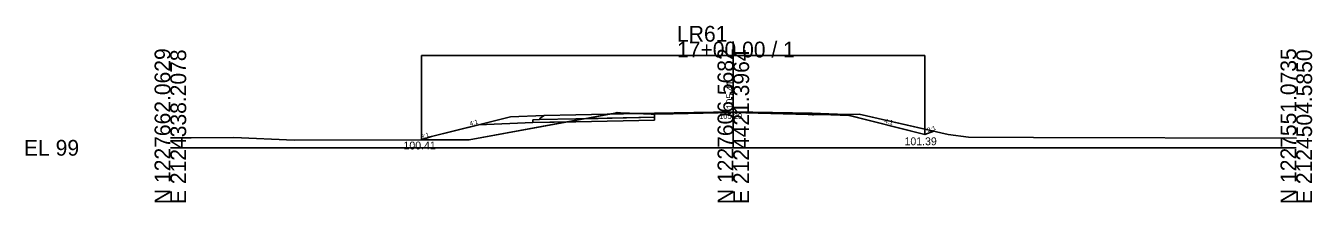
# Model space of a CAD drawing. Extents: x 2121193 to 2127979, y 1225108 to 1234639.
# Drawn here: x 2127750.9 to 2127979.4, y 1232107.5 to 1232138.9 of the extents above; entities that cross this region are included whole.
import ezdxf

# ---------------------------------------------------------------- set-up
doc = ezdxf.new("R2010")
doc.units = 0
for name, color, linetype in [('XS_CELL', 7, 'Continuous'), ('XS_M_DITCH', 7, 'Continuous'), ('XS_M_SHAPES_EARTHWORK', 7, 'Continuous'), ('XS_P_FINISHED_GRADE', 7, 'Continuous'), ('XS_P_FINISHED_GRADE_ELEV_TX', 7, 'Continuous'), ('XS_P_SUBGRADE_GRANULAR', 7, 'Continuous'), ('XS_P_SUBGRADE_LEVELING', 7, 'Continuous'), ('XS_P_SUBGRADE_PAVEMENT', 7, 'Continuous'), ('XS_P_TX_DCH', 7, 'Continuous'), ('XS_P_TX_FS_BS', 7, 'Continuous'), ('XS_X_GROUND', 7, 'Continuous'), ('XS_X_GROUND_TX', 7, 'Continuous')]:
    doc.layers.add(name, color=color, linetype=linetype)

msp = doc.modelspace()

# ---------------------------------------------------------------- linework, layer by layer
at = {"layer": 'XS_CELL'}
for p, q in [((2127876.61, 1232117.21), (2127876.61, 1232136.08)), ((2127776.61, 1232117.21), (2127876.61, 1232117.21)), ((2127876.61, 1232117.21), (2127976.61, 1232117.21))]:
    msp.add_line(p, q, dxfattribs=at)
at = {"layer": 'XS_M_DITCH'}
for p, q in [((2127821.24, 1232118.62), (2127821.24, 1232133.62)), ((2127821.24, 1232133.62), (2127910.61, 1232133.62)), ((2127910.61, 1232133.62), (2127910.61, 1232119.6))]:
    msp.add_line(p, q, dxfattribs=at)
at = {"layer": 'XS_M_SHAPES_EARTHWORK'}
for p, q in [((2127850.14, 1232122.38), (2127847.06, 1232121.82)), ((2127850.14, 1232122.38), (2127847.06, 1232121.82)), ((2127848.61, 1232121.85), (2127862.61, 1232122.13)), ((2127848.61, 1232121.85), (2127862.61, 1232122.13)), ((2127854.51, 1232123.18), (2127850.14, 1232122.38)), ((2127850.14, 1232122.38), (2127862.61, 1232122.63)), ((2127862.61, 1232122.63), (2127850.14, 1232122.38)), ((2127862.61, 1232122.63), (2127850.14, 1232122.38)), ((2127855.6, 1232123.38), (2127854.51, 1232123.18)), ((2127854.51, 1232123.18), (2127859.76, 1232123.28)), ((2127859.76, 1232123.28), (2127854.51, 1232123.18)), ((2127855.97, 1232123.47), (2127855.6, 1232123.38)), ((2127856.59, 1232123.44), (2127855.97, 1232123.47)), ((2127859.76, 1232123.28), (2127856.59, 1232123.44)), ((2127861.99, 1232123.17), (2127859.76, 1232123.28)), ((2127862.61, 1232123.18), (2127861.99, 1232123.17)), ((2127862.61, 1232122.63), (2127862.61, 1232123.18)), ((2127862.61, 1232122.13), (2127862.61, 1232122.63)), ((2127862.61, 1232122.13), (2127862.61, 1232122.63)), ((2127890.68, 1232123.21), (2127890.68, 1232123.08)), ((2127893.31, 1232123.11), (2127890.68, 1232123.21)), ((2127890.68, 1232123.08), (2127890.86, 1232123.07)), ((2127890.86, 1232123.07), (2127893.31, 1232123.11)), ((2127894.04, 1232123.12), (2127893.31, 1232123.11)), ((2127893.31, 1232123.11), (2127897.2, 1232122.95)), ((2127895.61, 1232123.14), (2127894.04, 1232123.12)), ((2127898.99, 1232123.19), (2127895.61, 1232123.14)), ((2127896.61, 1232123.1), (2127895.61, 1232123.14)), ((2127895.61, 1232123.14), (2127896.61, 1232123.1)), ((2127897.2, 1232122.95), (2127896.61, 1232123.1)), ((2127912.22, 1232120.14), (2127898.99, 1232123.19)), ((2127831.43, 1232121.32), (2127823, 1232119.21)), ((2127829.69, 1232118.65), (2127847.06, 1232121.82)), ((2127841, 1232121.7), (2127831.43, 1232121.32)), ((2127847.06, 1232121.82), (2127841, 1232121.7)), ((2127847.06, 1232121.82), (2127848.61, 1232121.85)), ((2127847.06, 1232121.82), (2127848.61, 1232121.85)), ((2127910.61, 1232119.6), (2127912.22, 1232120.14)), ((2127823, 1232119.21), (2127821.24, 1232118.62)), ((2127821.24, 1232118.62), (2127829.69, 1232118.65))]:
    msp.add_line(p, q, dxfattribs=at)
msp.add_lwpolyline([(2127896.61, 1232123.1), (2127897.2, 1232122.95), (2127910.61, 1232119.6)], dxfattribs=at)
at = {"layer": 'XS_P_FINISHED_GRADE'}
for p, q in [((2127837, 1232122.71), (2127823, 1232119.21)), ((2127843, 1232122.95), (2127837, 1232122.71)), ((2127848.61, 1232123.06), (2127843, 1232122.95)), ((2127862.61, 1232123.34), (2127848.61, 1232123.06)), ((2127876.61, 1232123.62), (2127862.61, 1232123.34)), ((2127876.61, 1232123.62), (2127890.61, 1232123.34)), ((2127890.61, 1232123.34), (2127896.61, 1232123.1)), ((2127896.61, 1232123.1), (2127910.61, 1232119.6)), ((2127910.61, 1232119.6), (2127912.22, 1232120.14)), ((2127823, 1232119.21), (2127821.24, 1232118.62))]:
    msp.add_line(p, q, dxfattribs=at)
at = {"layer": 'XS_P_SUBGRADE_GRANULAR'}
for p, q in [((2127842.17, 1232122.22), (2127841, 1232122.2)), ((2127841, 1232121.7), (2127841, 1232122.2)), ((2127862.61, 1232122.13), (2127848.61, 1232121.85)), ((2127862.61, 1232122.13), (2127862.61, 1232122.63)), ((2127890.68, 1232123.21), (2127897.2, 1232122.95)), ((2127841, 1232121.7), (2127831.43, 1232121.32)), ((2127848.61, 1232121.85), (2127841, 1232121.7))]:
    msp.add_line(p, q, dxfattribs=at)
at = {"layer": 'XS_P_SUBGRADE_LEVELING'}
for p, q in [((2127877.14, 1232123.48), (2127889.91, 1232123.11)), ((2127889.91, 1232123.11), (2127890.68, 1232123.08))]:
    msp.add_line(p, q, dxfattribs=at)
at = {"layer": 'XS_P_SUBGRADE_PAVEMENT'}
for p, q in [((2127842.32, 1232122.48), (2127842.17, 1232122.22)), ((2127848.61, 1232122.35), (2127842.17, 1232122.22)), ((2127843, 1232122.95), (2127842.32, 1232122.48)), ((2127862.61, 1232122.63), (2127848.61, 1232122.35)), ((2127876.61, 1232123.49), (2127862.61, 1232123.21)), ((2127862.61, 1232123.21), (2127862.61, 1232122.63)), ((2127876.61, 1232123.49), (2127890.68, 1232123.21)), ((2127890.61, 1232123.34), (2127890.68, 1232123.21))]:
    msp.add_line(p, q, dxfattribs=at)
at = {"layer": 'XS_X_GROUND'}
for p, q in [((2127829.69, 1232118.65), (2127855.6, 1232123.38)), ((2127855.6, 1232123.38), (2127855.97, 1232123.47)), ((2127855.97, 1232123.47), (2127856.59, 1232123.44)), ((2127856.59, 1232123.44), (2127861.99, 1232123.17)), ((2127861.99, 1232123.17), (2127865.93, 1232123.26)), ((2127865.93, 1232123.26), (2127876.61, 1232123.5)), ((2127876.61, 1232123.5), (2127889.91, 1232123.11)), ((2127889.91, 1232123.11), (2127890.86, 1232123.07)), ((2127890.86, 1232123.07), (2127894.04, 1232123.12)), ((2127894.04, 1232123.12), (2127898.99, 1232123.19)), ((2127898.99, 1232123.19), (2127914.75, 1232119.55)), ((2127776.64, 1232118.97), (2127780.29, 1232118.95)), ((2127780.29, 1232118.95), (2127787.86, 1232119.01)), ((2127787.86, 1232119.01), (2127798.6, 1232118.54)), ((2127798.6, 1232118.54), (2127829.69, 1232118.65)), ((2127914.75, 1232119.55), (2127918.4, 1232119.1)), ((2127918.4, 1232119.1), (2127929.95, 1232119.02)), ((2127929.95, 1232119.02), (2127976.64, 1232118.92))]:
    msp.add_line(p, q, dxfattribs=at)

# ---------------------------------------------------------------- texts
at = {"layer": 'XS_CELL'}
for s, p in [('LR61', (2127866.61, 1232136.08)), ('17+00.00 / 1', (2127866.61, 1232133.28)), ('EL 99', (2127750.61, 1232115.81))]:
    msp.add_text(s, height=2.8, dxfattribs=at).set_placement(p)
for s, p in [('N 1227662.0629', (2127776.61, 1232107.21)), ('E 2124338.2078', (2127779.41, 1232107.21)), ('N 1227606.5682', (2127876.61, 1232107.21)), ('E 2124421.3964', (2127879.41, 1232107.21)), ('N 1227551.0735', (2127976.61, 1232107.21)), ('E 2124504.5850', (2127979.41, 1232107.21))]:
    msp.add_text(s, height=2.8, rotation=90, dxfattribs=at).set_placement(p)
at = {"layer": 'XS_P_FINISHED_GRADE_ELEV_TX'}
msp.add_text(' 105.41', height=1.25, rotation=90, dxfattribs=at).set_placement((2127876.61, 1232123.62))
at = {"layer": 'XS_P_TX_DCH'}
for s, p in [('100.41', (2127818.02, 1232116.91)), ('101.39', (2127907.02, 1232117.66))]:
    msp.add_text(s, height=1.4, dxfattribs=at).set_placement(p)
at = {"layer": 'XS_P_TX_FS_BS'}
for s, rotation, p in [('4:1', 14.0362, (2127829.85, 1232121.11)), ('4:1', 345.9638, (2127903.38, 1232121.66)), ('3:1', 18.4349, (2127821.23, 1232118.74)), ('3:1', 18.4349, (2127911.21, 1232119.94))]:
    msp.add_text(s, height=0.8, rotation=rotation, dxfattribs=at).set_placement(p)
at = {"layer": 'XS_X_GROUND_TX'}
msp.add_text('105.29', height=1, dxfattribs=at).set_placement((2127874.08, 1232122.34))

doc.saveas('drawing.dxf')
